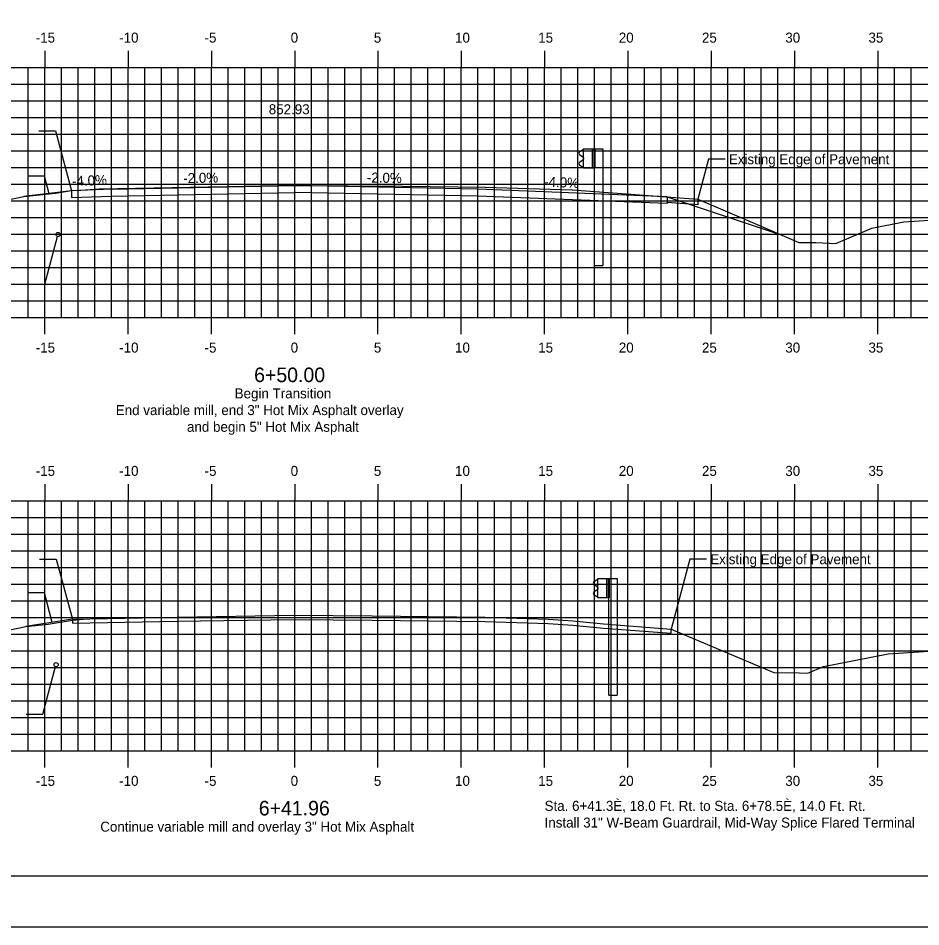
# Model space of a CAD drawing. Extents: x 2193811 to 2194294, y 863888 to 863998.
# Drawn here: x 2194016.6 to 2194070.8, y 863888.4 to 863942.9 of the extents above; entities that cross this region are included whole.
import ezdxf

# ---------------------------------------------------------------- set-up
doc = ezdxf.new("R2010")
doc.units = 0
for name, color, linetype in [('ANNOTATION', 7, 'Continuous'), ('BORDER', 7, 'Continuous'), ('D_Guardrail_Beam_Lt', 7, 'Continuous'), ('D_Guardrail_Beam_Rt', 7, 'Continuous'), ('H_V ANNOTATION', 7, 'Continuous'), ('MAJOR', 7, 'Continuous'), ('MINOR', 7, 'Continuous'), ('PLOT BOUNDARY', 7, 'Continuous'), ('S_Roadway_Centerline', 7, 'Continuous'), ('S_Utilities_Pole_Power', 7, 'Continuous'), ('TEMPLATE', 7, 'Continuous')]:
    doc.layers.add(name, color=color, linetype=linetype)

msp = doc.modelspace()

# ---------------------------------------------------------------- linework, layer by layer
at = {"layer": 'ANNOTATION'}
for points in [[(2194017.871, 863936.148), (2194018.871, 863936.148), (2194019.833, 863932.56)], [(2194059.074, 863934.446), (2194058.074, 863934.446), (2194057.431, 863932.047)], [(2194017.183, 863933.446), (2194018.183, 863933.446), (2194018.183, 863933.446), (2194018.465, 863932.396)], [(2194017.231, 863926.958), (2194018.231, 863926.958), (2194018.995, 863929.811)], [(2194017.922, 863910.446), (2194018.922, 863910.446), (2194019.884, 863906.857)], [(2194057.953, 863910.446), (2194056.953, 863910.446), (2194055.831, 863906.258)], [(2194017.183, 863908.446), (2194018.183, 863908.446), (2194018.183, 863908.446), (2194018.661, 863906.662)], [(2194017.111, 863901.148), (2194018.111, 863901.148), (2194018.875, 863904.002)]]:
    msp.add_lwpolyline(points, dxfattribs=at)
at = {"layer": 'BORDER'}
msp.add_lwpolyline([(2193958.23, 863891.446), (2194118.23, 863891.446), (2194118.23, 863996.446), (2193958.23, 863996.446)], close=True, dxfattribs=at)
at = {"layer": 'D_Guardrail_Beam_Lt'}
for p, q in [((2194050.473, 863934.975), (2194050.329, 863934.875)), ((2194050.329, 863934.732), (2194050.524, 863934.596)), ((2194050.562, 863934.997), (2194050.488, 863934.982)), ((2194050.562, 863935.08), (2194051.25, 863935.08)), ((2194050.562, 863933.913), (2194050.562, 863935.08)), ((2194051.083, 863935.08), (2194051.083, 863933.913)), ((2194051.187, 863935.08), (2194051.187, 863933.913)), ((2194051.25, 863935.08), (2194051.721, 863935.08)), ((2194051.25, 863935.08), (2194051.25, 863933.913)), ((2194051.721, 863935.08), (2194051.721, 863928.08)), ((2194050.524, 863934.397), (2194050.329, 863934.261)), ((2194050.558, 863934.532), (2194050.558, 863934.461)), ((2194050.329, 863934.118), (2194050.473, 863934.018)), ((2194050.488, 863934.011), (2194050.562, 863933.997)), ((2194051.25, 863933.913), (2194050.562, 863933.913)), ((2194051.229, 863928.08), (2194051.229, 863933.913)), ((2194051.229, 863928.08), (2194051.721, 863928.08))]:
    msp.add_line(p, q, dxfattribs=at)
for centre, major_axis, start_param, end_param in [((2194050.379, 863934.804), (-0.0877, 0), 5.323254, 7.243116), ((2194050.496, 863934.941), (-0.0417, 0), 4.907132, 5.323254), ((2194050.379, 863934.189), (-0.0877, 0), 5.323254, 7.243116), ((2194050.479, 863934.532), (0.0789, 0), 0, 0.959931), ((2194050.479, 863934.461), (0.0789, 0), 5.323254, 6.283185), ((2194050.496, 863934.052), (-0.0417, 0), 0.959931, 1.376053)]:
    msp.add_ellipse(centre, major_axis=major_axis, ratio=0.995501, start_param=start_param, end_param=end_param, dxfattribs=at)
at = {"layer": 'D_Guardrail_Beam_Rt'}
for p, q in [((2194051.336, 863909.182), (2194051.192, 863909.082)), ((2194051.425, 863909.204), (2194051.351, 863909.189)), ((2194051.425, 863909.287), (2194052.113, 863909.287)), ((2194051.425, 863908.12), (2194051.425, 863909.287)), ((2194051.946, 863909.287), (2194051.946, 863908.12)), ((2194052.05, 863909.287), (2194052.05, 863908.12)), ((2194052.113, 863909.287), (2194052.584, 863909.287)), ((2194052.113, 863909.287), (2194052.113, 863908.12)), ((2194052.584, 863909.287), (2194052.584, 863902.287)), ((2194051.192, 863908.939), (2194051.387, 863908.803)), ((2194051.387, 863908.604), (2194051.192, 863908.468)), ((2194051.421, 863908.739), (2194051.421, 863908.669)), ((2194051.192, 863908.325), (2194051.336, 863908.225)), ((2194051.351, 863908.218), (2194051.425, 863908.204)), ((2194052.113, 863908.12), (2194051.425, 863908.12)), ((2194052.092, 863902.287), (2194052.092, 863908.12)), ((2194052.092, 863902.287), (2194052.584, 863902.287))]:
    msp.add_line(p, q, dxfattribs=at)
for centre, major_axis, start_param, end_param in [((2194051.242, 863909.011), (-0.0877, 0), 5.323254, 7.243116), ((2194051.359, 863909.148), (-0.0417, 0), 4.907132, 5.323254), ((2194051.342, 863908.739), (0.0789, 0), 0, 0.959931), ((2194051.342, 863908.669), (0.0789, 0), 5.323254, 6.283185), ((2194051.242, 863908.396), (-0.0877, 0), 5.323254, 7.243116), ((2194051.359, 863908.259), (-0.0417, 0), 0.959931, 1.376053)]:
    msp.add_ellipse(centre, major_axis=major_axis, ratio=0.995501, start_param=start_param, end_param=end_param, dxfattribs=at)
at = {"layer": 'MAJOR'}
for p, q in [((2194018.23, 863940.948), (2194018.23, 863939.946)), ((2194023.23, 863940.948), (2194023.23, 863939.946)), ((2194028.23, 863940.948), (2194028.23, 863939.946)), ((2194033.23, 863940.948), (2194033.23, 863939.946)), ((2194038.23, 863940.948), (2194038.23, 863939.946)), ((2194043.23, 863940.948), (2194043.23, 863939.946)), ((2194048.23, 863940.948), (2194048.23, 863939.946)), ((2194053.23, 863940.948), (2194053.23, 863939.946)), ((2194058.23, 863940.948), (2194058.23, 863939.946)), ((2194063.23, 863940.948), (2194063.23, 863939.946)), ((2194068.23, 863940.948), (2194068.23, 863939.946)), ((2193963.23, 863939.946), (2194103.23, 863939.946)), ((2193963.23, 863939.946), (2194103.23, 863939.946)), ((2194018.23, 863924.946), (2194018.23, 863939.946)), ((2194023.23, 863924.946), (2194023.23, 863939.946)), ((2194028.23, 863924.946), (2194028.23, 863939.946)), ((2194033.23, 863924.946), (2194033.23, 863939.946)), ((2194038.23, 863924.946), (2194038.23, 863939.946)), ((2194043.23, 863924.946), (2194043.23, 863939.946)), ((2194048.23, 863924.946), (2194048.23, 863939.946)), ((2194053.23, 863924.946), (2194053.23, 863939.946)), ((2194058.23, 863924.946), (2194058.23, 863939.946)), ((2194063.23, 863924.946), (2194063.23, 863939.946)), ((2194068.23, 863924.946), (2194068.23, 863939.946)), ((2193963.23, 863934.946), (2194103.23, 863934.946)), ((2193963.23, 863929.946), (2194103.23, 863929.946)), ((2193963.23, 863924.946), (2194103.23, 863924.946)), ((2194018.23, 863923.944), (2194018.23, 863924.946)), ((2194023.23, 863923.944), (2194023.23, 863924.946)), ((2194028.23, 863923.944), (2194028.23, 863924.946)), ((2194033.23, 863923.944), (2194033.23, 863924.946)), ((2194038.23, 863923.944), (2194038.23, 863924.946)), ((2194043.23, 863923.944), (2194043.23, 863924.946)), ((2194048.23, 863923.944), (2194048.23, 863924.946)), ((2194053.23, 863923.944), (2194053.23, 863924.946)), ((2194058.23, 863923.944), (2194058.23, 863924.946)), ((2194063.23, 863923.944), (2194063.23, 863924.946)), ((2194068.23, 863923.944), (2194068.23, 863924.946)), ((2194018.23, 863914.948), (2194018.23, 863913.946)), ((2194023.23, 863914.948), (2194023.23, 863913.946)), ((2194028.23, 863914.948), (2194028.23, 863913.946)), ((2194033.23, 863914.948), (2194033.23, 863913.946)), ((2194038.23, 863914.948), (2194038.23, 863913.946)), ((2194043.23, 863914.948), (2194043.23, 863913.946)), ((2194048.23, 863914.948), (2194048.23, 863913.946)), ((2194053.23, 863914.948), (2194053.23, 863913.946)), ((2194058.23, 863914.948), (2194058.23, 863913.946)), ((2194063.23, 863914.948), (2194063.23, 863913.946)), ((2194068.23, 863914.948), (2194068.23, 863913.946)), ((2193963.23, 863913.946), (2194103.23, 863913.946)), ((2193963.23, 863913.946), (2194103.23, 863913.946)), ((2194018.23, 863898.946), (2194018.23, 863913.946)), ((2194023.23, 863898.946), (2194023.23, 863913.946)), ((2194028.23, 863898.946), (2194028.23, 863913.946)), ((2194033.23, 863898.946), (2194033.23, 863913.946)), ((2194038.23, 863898.946), (2194038.23, 863913.946)), ((2194043.23, 863898.946), (2194043.23, 863913.946)), ((2194048.23, 863898.946), (2194048.23, 863913.946)), ((2194053.23, 863898.946), (2194053.23, 863913.946)), ((2194058.23, 863898.946), (2194058.23, 863913.946)), ((2194063.23, 863898.946), (2194063.23, 863913.946)), ((2194068.23, 863898.946), (2194068.23, 863913.946)), ((2193963.23, 863908.946), (2194103.23, 863908.946)), ((2193963.23, 863903.946), (2194103.23, 863903.946)), ((2193963.23, 863898.946), (2194103.23, 863898.946)), ((2194018.23, 863897.944), (2194018.23, 863898.946)), ((2194023.23, 863897.944), (2194023.23, 863898.946)), ((2194028.23, 863897.944), (2194028.23, 863898.946)), ((2194033.23, 863897.944), (2194033.23, 863898.946)), ((2194038.23, 863897.944), (2194038.23, 863898.946)), ((2194043.23, 863897.944), (2194043.23, 863898.946)), ((2194048.23, 863897.944), (2194048.23, 863898.946)), ((2194053.23, 863897.944), (2194053.23, 863898.946)), ((2194058.23, 863897.944), (2194058.23, 863898.946)), ((2194063.23, 863897.944), (2194063.23, 863898.946)), ((2194068.23, 863897.944), (2194068.23, 863898.946))]:
    msp.add_line(p, q, dxfattribs=at)
at = {"layer": 'MINOR'}
for p, q in [((2194017.23, 863924.946), (2194017.23, 863939.946)), ((2194019.23, 863924.946), (2194019.23, 863939.946)), ((2194020.23, 863924.946), (2194020.23, 863939.946)), ((2194021.23, 863924.946), (2194021.23, 863939.946)), ((2194022.23, 863924.946), (2194022.23, 863939.946)), ((2194024.23, 863924.946), (2194024.23, 863939.946)), ((2194025.23, 863924.946), (2194025.23, 863939.946)), ((2194026.23, 863924.946), (2194026.23, 863939.946)), ((2194027.23, 863924.946), (2194027.23, 863939.946)), ((2194029.23, 863924.946), (2194029.23, 863939.946)), ((2194030.23, 863924.946), (2194030.23, 863939.946)), ((2194031.23, 863924.946), (2194031.23, 863939.946)), ((2194032.23, 863924.946), (2194032.23, 863939.946)), ((2194034.23, 863924.946), (2194034.23, 863939.946)), ((2194035.23, 863924.946), (2194035.23, 863939.946)), ((2194036.23, 863924.946), (2194036.23, 863939.946)), ((2194037.23, 863924.946), (2194037.23, 863939.946)), ((2194039.23, 863924.946), (2194039.23, 863939.946)), ((2194040.23, 863924.946), (2194040.23, 863939.946)), ((2194041.23, 863924.946), (2194041.23, 863939.946)), ((2194042.23, 863924.946), (2194042.23, 863939.946)), ((2194044.23, 863924.946), (2194044.23, 863939.946)), ((2194045.23, 863924.946), (2194045.23, 863939.946)), ((2194046.23, 863924.946), (2194046.23, 863939.946)), ((2194047.23, 863924.946), (2194047.23, 863939.946)), ((2194049.23, 863924.946), (2194049.23, 863939.946)), ((2194050.23, 863924.946), (2194050.23, 863939.946)), ((2194051.23, 863924.946), (2194051.23, 863939.946)), ((2194052.23, 863924.946), (2194052.23, 863939.946)), ((2194054.23, 863924.946), (2194054.23, 863939.946)), ((2194055.23, 863924.946), (2194055.23, 863939.946)), ((2194056.23, 863924.946), (2194056.23, 863939.946)), ((2194057.23, 863924.946), (2194057.23, 863939.946)), ((2194059.23, 863924.946), (2194059.23, 863939.946)), ((2194060.23, 863924.946), (2194060.23, 863939.946)), ((2194061.23, 863924.946), (2194061.23, 863939.946)), ((2194062.23, 863924.946), (2194062.23, 863939.946)), ((2194064.23, 863924.946), (2194064.23, 863939.946)), ((2194065.23, 863924.946), (2194065.23, 863939.946)), ((2194066.23, 863924.946), (2194066.23, 863939.946)), ((2194067.23, 863924.946), (2194067.23, 863939.946)), ((2194069.23, 863924.946), (2194069.23, 863939.946)), ((2194070.23, 863924.946), (2194070.23, 863939.946)), ((2193963.23, 863938.946), (2194103.23, 863938.946)), ((2193963.23, 863937.946), (2194103.23, 863937.946)), ((2193963.23, 863936.946), (2194103.23, 863936.946)), ((2193963.23, 863935.946), (2194103.23, 863935.946)), ((2193963.23, 863933.946), (2194103.23, 863933.946)), ((2193963.23, 863932.946), (2194103.23, 863932.946)), ((2193963.23, 863931.946), (2194103.23, 863931.946)), ((2193963.23, 863930.946), (2194103.23, 863930.946)), ((2193963.23, 863928.946), (2194103.23, 863928.946)), ((2193963.23, 863927.946), (2194103.23, 863927.946)), ((2193963.23, 863926.946), (2194103.23, 863926.946)), ((2193963.23, 863925.946), (2194103.23, 863925.946)), ((2194017.23, 863898.946), (2194017.23, 863913.946)), ((2194019.23, 863898.946), (2194019.23, 863913.946)), ((2194020.23, 863898.946), (2194020.23, 863913.946)), ((2194021.23, 863898.946), (2194021.23, 863913.946)), ((2194022.23, 863898.946), (2194022.23, 863913.946)), ((2194024.23, 863898.946), (2194024.23, 863913.946)), ((2194025.23, 863898.946), (2194025.23, 863913.946)), ((2194026.23, 863898.946), (2194026.23, 863913.946)), ((2194027.23, 863898.946), (2194027.23, 863913.946)), ((2194029.23, 863898.946), (2194029.23, 863913.946)), ((2194030.23, 863898.946), (2194030.23, 863913.946)), ((2194031.23, 863898.946), (2194031.23, 863913.946)), ((2194032.23, 863898.946), (2194032.23, 863913.946)), ((2194034.23, 863898.946), (2194034.23, 863913.946)), ((2194035.23, 863898.946), (2194035.23, 863913.946)), ((2194036.23, 863898.946), (2194036.23, 863913.946)), ((2194037.23, 863898.946), (2194037.23, 863913.946)), ((2194039.23, 863898.946), (2194039.23, 863913.946)), ((2194040.23, 863898.946), (2194040.23, 863913.946)), ((2194041.23, 863898.946), (2194041.23, 863913.946)), ((2194042.23, 863898.946), (2194042.23, 863913.946)), ((2194044.23, 863898.946), (2194044.23, 863913.946)), ((2194045.23, 863898.946), (2194045.23, 863913.946)), ((2194046.23, 863898.946), (2194046.23, 863913.946)), ((2194047.23, 863898.946), (2194047.23, 863913.946)), ((2194049.23, 863898.946), (2194049.23, 863913.946)), ((2194050.23, 863898.946), (2194050.23, 863913.946)), ((2194051.23, 863898.946), (2194051.23, 863913.946)), ((2194052.23, 863898.946), (2194052.23, 863913.946)), ((2194054.23, 863898.946), (2194054.23, 863913.946)), ((2194055.23, 863898.946), (2194055.23, 863913.946)), ((2194056.23, 863898.946), (2194056.23, 863913.946)), ((2194057.23, 863898.946), (2194057.23, 863913.946)), ((2194059.23, 863898.946), (2194059.23, 863913.946)), ((2194060.23, 863898.946), (2194060.23, 863913.946)), ((2194061.23, 863898.946), (2194061.23, 863913.946)), ((2194062.23, 863898.946), (2194062.23, 863913.946)), ((2194064.23, 863898.946), (2194064.23, 863913.946)), ((2194065.23, 863898.946), (2194065.23, 863913.946)), ((2194066.23, 863898.946), (2194066.23, 863913.946)), ((2194067.23, 863898.946), (2194067.23, 863913.946)), ((2194069.23, 863898.946), (2194069.23, 863913.946)), ((2194070.23, 863898.946), (2194070.23, 863913.946)), ((2193963.23, 863912.946), (2194103.23, 863912.946)), ((2193963.23, 863911.946), (2194103.23, 863911.946)), ((2193963.23, 863910.946), (2194103.23, 863910.946)), ((2193963.23, 863909.946), (2194103.23, 863909.946)), ((2193963.23, 863907.946), (2194103.23, 863907.946)), ((2193963.23, 863906.946), (2194103.23, 863906.946)), ((2193963.23, 863905.946), (2194103.23, 863905.946)), ((2193963.23, 863904.946), (2194103.23, 863904.946)), ((2193963.23, 863902.946), (2194103.23, 863902.946)), ((2193963.23, 863901.946), (2194103.23, 863901.946)), ((2193963.23, 863900.946), (2194103.23, 863900.946)), ((2193963.23, 863899.946), (2194103.23, 863899.946))]:
    msp.add_line(p, q, dxfattribs=at)
at = {"layer": 'PLOT BOUNDARY'}
msp.add_lwpolyline([(2193950.137, 863888.387), (2194120.137, 863888.387), (2194120.137, 863998.387), (2193950.137, 863998.387)], close=True, dxfattribs=at)
at = {"layer": 'S_Roadway_Centerline'}
for points in [[(2194007.204, 863930.189), (2194016.97, 863932.216), (2194018.864, 863932.405), (2194019.833, 863932.563), (2194020.39, 863932.594), (2194021.489, 863932.677), (2194028.066, 863932.795), (2194033.187, 863932.876), (2194039.712, 863932.827), (2194044.659, 863932.763), (2194049.894, 863932.607), (2194049.898, 863932.607), (2194049.904, 863932.606), (2194057.431, 863932.047), (2194060.719, 863930.654), (2194063.5, 863929.453), (2194064.503, 863929.448), (2194065.709, 863929.388), (2194067.87, 863930.316), (2194069.789, 863930.696), (2194094.683, 863932.303), (2194100.066, 863932.516), (2194103.23, 863932.52)], [(2194057.431, 863932.047), (2194057.431, 863931.714), (2194055.589, 863931.851)], [(2193963.23, 863903.335), (2193972.487, 863903.387), (2193972.709, 863903.336), (2193975.387, 863903.366), (2193977.316, 863903.378), (2193999.693, 863903.176), (2193999.824, 863903.182), (2194010.154, 863904.971), (2194017.091, 863906.411), (2194018.437, 863906.546), (2194019.884, 863906.782), (2194020.782, 863906.873)], [(2194055.831, 863906.258), (2194060.848, 863904.133), (2194061.992, 863903.639), (2194063.508, 863903.631), (2194064.033, 863903.605), (2194064.974, 863904.009), (2194068.845, 863904.776), (2194087.811, 863906), (2194098.514, 863906.424), (2194103.23, 863906.43)]]:
    msp.add_lwpolyline(points, dxfattribs=at)
at = {"layer": 'S_Utilities_Pole_Power'}
for centre in [(2194019.028, 863929.932), (2194018.908, 863904.122)]:
    msp.add_circle(centre, 0.125, dxfattribs=at)
at = {"layer": 'TEMPLATE'}
for p, q in [((2194019.833, 863932.56), (2194016.97, 863932.216)), ((2194022.23, 863932.656), (2194033.23, 863932.876)), ((2194022.23, 863932.239), (2194033.23, 863932.459)), ((2194044.23, 863932.239), (2194033.23, 863932.459)), ((2194055.589, 863932.201), (2194062.372, 863929.94)), ((2194019.884, 863906.857), (2194017.091, 863906.411)), ((2194055.831, 863906.008), (2194055.831, 863906.258))]:
    msp.add_line(p, q, dxfattribs=at)
for points in [[(2194055.589, 863932.201), (2194044.23, 863932.656), (2194033.23, 863932.876), (2194022.23, 863932.656), (2194019.833, 863932.56)], [(2194019.833, 863932.56), (2194019.833, 863932.143), (2194022.23, 863932.239)], [(2194055.589, 863932.201), (2194055.589, 863931.785), (2194044.23, 863932.239)], [(2194019.884, 863906.857), (2194026.179, 863906.97), (2194033.194, 863907.082), (2194037.875, 863907.046), (2194044.666, 863906.959), (2194048.45, 863906.847), (2194049.935, 863906.741), (2194051.771, 863906.559), (2194055.831, 863906.258)], [(2194019.884, 863906.857), (2194019.884, 863906.607), (2194026.179, 863906.72), (2194033.194, 863906.832), (2194037.875, 863906.796), (2194044.666, 863906.709), (2194048.45, 863906.597), (2194049.935, 863906.491), (2194051.771, 863906.309), (2194055.831, 863906.008)]]:
    msp.add_lwpolyline(points, dxfattribs=at)

# ---------------------------------------------------------------- texts
at = {"layer": 'ANNOTATION'}
for s, p in [('852.93', (2194031.675, 863937.146)), ('Existing Edge of Pavement', (2194059.29, 863934.146)), ('Begin Transition', (2194029.628, 863920.096)), ('End variable mill, end 3" Hot Mix Asphalt overlay', (2194022.493, 863919.094)), ('and begin 5" Hot Mix Asphalt', (2194026.766, 863918.092)), ('Existing Edge of Pavement', (2194058.17, 863910.146)), ('Sta. 6+41.3È, 18.0 Ft. Rt. to Sta. 6+78.5È, 14.0 Ft. Rt.', (2194048.23, 863895.346)), ('Install 31" W-Beam Guardrail, Mid-Way Splice Flared Terminal', (2194048.23, 863894.344)), ('Continue variable mill and overlay 3" Hot Mix Asphalt', (2194021.56, 863894.096))]:
    msp.add_text(s, height=0.6, dxfattribs=at).set_placement(p)
for s, rotation, p in [('-2.0%', 1.1458, (2194026.547, 863933.009)), ('-2.0%', 358.8542, (2194037.558, 863933.056)), ('-4.0%', 2.2906, (2194019.876, 863932.829)), ('-4.0%', 357.7094, (2194048.193, 863932.804))]:
    msp.add_text(s, height=0.6, rotation=rotation, dxfattribs=at).set_placement(p)
at = {"layer": 'H_V ANNOTATION'}
for s, height, p in [('-15', 0.6, (2194017.687, 863941.446)), ('-10', 0.6, (2194022.695, 863941.446)), ('-5', 0.6, (2194027.82, 863941.446)), ('0', 0.6, (2194032.989, 863941.446)), ('5', 0.6, (2194037.981, 863941.446)), ('10', 0.6, (2194042.855, 863941.446)), ('15', 0.6, (2194047.847, 863941.446)), ('20', 0.6, (2194052.684, 863941.446)), ('25', 0.6, (2194057.676, 863941.446)), ('30', 0.6, (2194062.678, 863941.446)), ('35', 0.6, (2194067.67, 863941.446)), ('-15', 0.6, (2194017.687, 863922.846)), ('-10', 0.6, (2194022.695, 863922.846)), ('-5', 0.6, (2194027.82, 863922.846)), ('0', 0.6, (2194032.989, 863922.846)), ('5', 0.6, (2194037.981, 863922.846)), ('10', 0.6, (2194042.855, 863922.846)), ('15', 0.6, (2194047.847, 863922.846)), ('20', 0.6, (2194052.684, 863922.846)), ('25', 0.6, (2194057.676, 863922.846)), ('30', 0.6, (2194062.678, 863922.846)), ('35', 0.6, (2194067.67, 863922.846)), ('6+50.00', 0.875, (2194030.795, 863921.071)), ('-15', 0.6, (2194017.687, 863915.446)), ('-10', 0.6, (2194022.695, 863915.446)), ('-5', 0.6, (2194027.82, 863915.446)), ('0', 0.6, (2194032.989, 863915.446)), ('5', 0.6, (2194037.981, 863915.446)), ('10', 0.6, (2194042.855, 863915.446)), ('15', 0.6, (2194047.847, 863915.446)), ('20', 0.6, (2194052.684, 863915.446)), ('25', 0.6, (2194057.676, 863915.446)), ('30', 0.6, (2194062.678, 863915.446)), ('35', 0.6, (2194067.67, 863915.446)), ('-15', 0.6, (2194017.687, 863896.846)), ('-10', 0.6, (2194022.695, 863896.846)), ('-5', 0.6, (2194027.82, 863896.846)), ('0', 0.6, (2194032.989, 863896.846)), ('5', 0.6, (2194037.981, 863896.846)), ('10', 0.6, (2194042.855, 863896.846)), ('15', 0.6, (2194047.847, 863896.846)), ('20', 0.6, (2194052.684, 863896.846)), ('25', 0.6, (2194057.676, 863896.846)), ('30', 0.6, (2194062.678, 863896.846)), ('35', 0.6, (2194067.67, 863896.846)), ('6+41.96', 0.875, (2194031.076, 863895.071))]:
    msp.add_text(s, height=height, dxfattribs=at).set_placement(p)

doc.saveas('drawing.dxf')
